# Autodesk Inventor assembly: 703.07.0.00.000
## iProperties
Created: 2005-05
Part Number: 703.07.0.00.000
Document SubType Name: Assembly
Designer: tfa
Manufacturer: Standard
Standards Organization: Custom
Description: Pneumatikführung,D=40,H=200
Author: tfa
